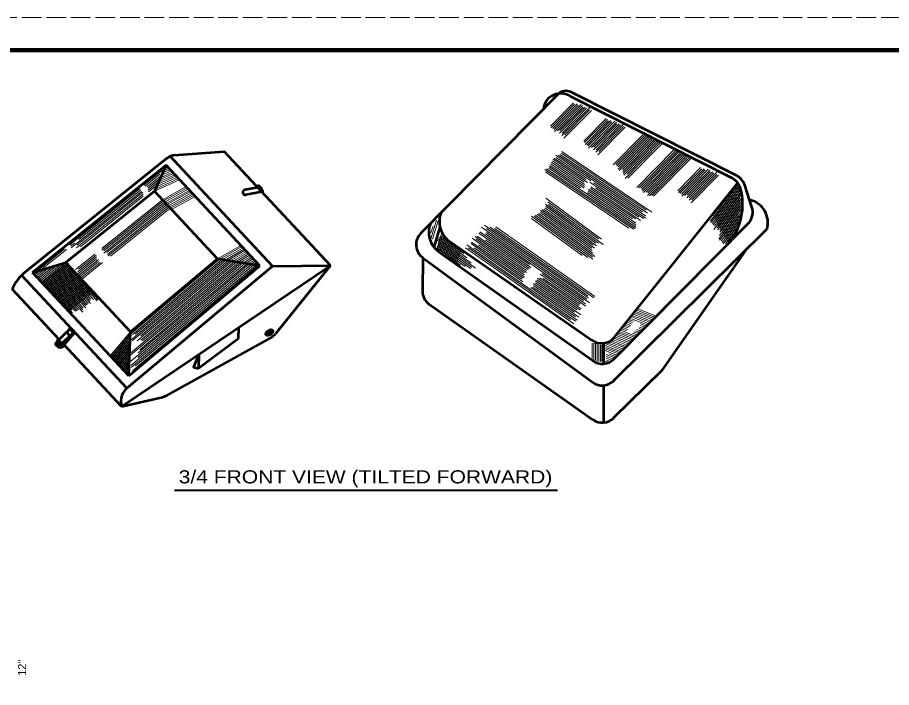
# Model space of a CAD drawing. Extents: x -67 to 613, y -55 to 385.
# Drawn here: x 119.2 to 386.2, y 179.9 to 384.6 of the extents above; entities that cross this region are included whole.
import ezdxf

# ---------------------------------------------------------------- set-up
doc = ezdxf.new("R2010")
doc.units = 0
doc.linetypes.add('LONG_DASHED', pattern=[7.5, 6, -1.5])
doc.layers.add('1', color=7, linetype='Continuous', lineweight=13)
doc.layers.add('61', color=7, linetype='Continuous', lineweight=35)

msp = doc.modelspace()

# ---------------------------------------------------------------- linework, layer by layer
at = {"layer": '1', "lineweight": 53}
for p, q in [((242.429, 318.693), (284.722, 361.553)), ((338.855, 336.269), (288.755, 361.588)), ((337.504, 335.457), (288.089, 360.43)), ((197.065, 308.614), (165.693, 342.257)), ((166.939, 342.485), (182.369, 343.629)), ((214.86, 308.786), (182.369, 343.629)), ((164.707, 341.463), (121.696, 306.859)), ((164.571, 339.428), (123.814, 306.638)), ((164.571, 339.428), (161.056, 331.467)), ((193.249, 308.675), (164.571, 339.428)), ((301.482, 286.796), (339.241, 334.004)), ((161.056, 331.467), (133.971, 309.675)), ((180.282, 310.849), (161.056, 331.467)), ((192.643, 332.611), (188.705, 331.907)), ((193.861, 331.305), (188.969, 330.43)), ((192.643, 332.611), (192.643, 333.478)), ((192.643, 333.478), (193.861, 332.172)), ((192.643, 333.111), (193.861, 331.805)), ((193.861, 331.305), (193.861, 332.172)), ((343.558, 326.638), (341.351, 333.365)), ((248.263, 320.485), (246.399, 314.394)), ((301.399, 280.208), (342.324, 321.525)), ((301.284, 273.599), (348.185, 319.998)), ((250.594, 316.631), (294.693, 285.981)), ((247.916, 312.964), (294.923, 279.733)), ((153.687, 288.533), (180.282, 310.849)), ((193.249, 308.675), (180.282, 310.849)), ((243.028, 311.151), (242.889, 301.051)), ((243.028, 311.151), (294.808, 273.124)), ((123.814, 306.638), (133.971, 309.675)), ((153.687, 288.533), (133.971, 309.675)), ((151.024, 265.729), (214.86, 308.786)), ((153.229, 275.094), (193.249, 308.675)), ((214.86, 308.786), (198.026, 287.947)), ((152.635, 271.333), (120.47, 305.825)), ((153.229, 275.094), (123.814, 306.638)), ((131.907, 286.229), (117.606, 301.565)), ((294.834, 261.694), (245.003, 296.898)), ((134.136, 288.39), (131.684, 286.012)), ((134.136, 288.39), (135.18, 287.313)), ((135.139, 289.525), (136.183, 288.448)), ((153.229, 275.094), (153.687, 288.533)), ((186.673, 289.774), (186.625, 286.395)), ((195.047, 287.697), (197.024, 289.115)), ((195.193, 287.494), (197.17, 288.912)), ((132.433, 284.609), (131.332, 285.71)), ((132.745, 284.951), (131.684, 286.012)), ((135.18, 287.313), (132.745, 284.951)), ((136.466, 288.11), (133.181, 284.291)), ((164.792, 269.106), (196.561, 286.715)), ((186.625, 286.395), (174.495, 277.305)), ((131.996, 283.561), (130.731, 284.719)), ((132.315, 283.962), (130.976, 285.188)), ((133.767, 284.235), (131.996, 283.561)), ((133.181, 284.291), (132.085, 283.874)), ((151.024, 265.729), (133.437, 284.588)), ((298.249, 285.047), (298.249, 278.776)), ((174.556, 281.601), (174.495, 277.305)), ((298.249, 272.177), (298.249, 260.805)), ((151.024, 265.729), (163.493, 268.607))]:
    msp.add_line(p, q, dxfattribs=at)
at = {"layer": '1'}
for p, q in [((282.068, 351.398), (289.033, 358.456)), ((282.248, 350.868), (289.389, 358.105)), ((282.724, 350.639), (290.118, 358.132)), ((283.255, 349.753), (291.355, 357.962)), ((283.175, 350.384), (290.426, 357.732)), ((284.158, 349.957), (291.801, 357.702)), ((284.815, 349.198), (292.654, 357.142)), ((284.908, 350.005), (291.964, 357.155)), ((285.522, 348.492), (293.987, 357.069)), ((285.565, 349.247), (293.058, 356.84)), ((286.127, 347.681), (294.502, 356.168)), ((286.394, 348.663), (293.954, 356.324)), ((292.218, 346.825), (299.033, 353.731)), ((292.423, 346.321), (299.388, 353.38)), ((292.603, 345.792), (299.744, 353.029)), ((293.079, 345.562), (300.474, 353.056)), ((293.531, 345.308), (300.782, 352.656)), ((293.611, 344.677), (301.711, 352.886)), ((294.514, 344.88), (302.157, 352.626)), ((295.17, 344.122), (303.009, 352.066)), ((295.264, 344.928), (302.32, 352.079)), ((295.878, 343.416), (304.342, 351.993)), ((295.92, 344.17), (303.413, 351.764)), ((296.483, 342.605), (304.858, 351.092)), ((296.75, 343.587), (304.309, 351.248)), ((301.143, 339.497), (310.259, 348.735)), ((302.018, 339.672), (310.86, 348.632)), ((302.248, 339.193), (311.41, 348.478)), ((302.677, 338.916), (311.887, 348.25)), ((302.706, 338.233), (312.142, 347.796)), ((302.99, 337.809), (312.645, 347.594)), ((304.007, 338.128), (313.074, 347.316)), ((304.115, 337.525), (313.674, 347.212)), ((304.244, 336.944), (314.103, 346.935)), ((304.375, 336.366), (314.533, 346.66)), ((304.834, 335.407), (315.636, 346.353)), ((305.423, 336.715), (315.158, 346.581)), ((305.608, 335.479), (315.987, 345.998)), ((283.667, 342.454), (311.085, 323.959)), ((283.766, 341.784), (294.327, 334.66)), ((284.512, 342.487), (310.081, 325.239)), ((285.014, 342.751), (311.648, 324.785)), ((285.347, 343.13), (311.215, 325.68)), ((285.519, 343.617), (312.943, 325.118)), ((308.36, 332.574), (319.733, 344.099)), ((309.038, 332.548), (320.384, 344.047)), ((309.565, 332.37), (320.764, 343.72)), ((309.921, 332.019), (321.267, 343.517)), ((310.073, 331.462), (321.496, 343.038)), ((310.401, 331.083), (322.125, 342.963)), ((311.205, 331.185), (322.627, 342.76)), ((311.659, 330.222), (323.485, 342.206)), ((311.73, 331.006), (322.981, 342.407)), ((312.239, 330.097), (323.765, 341.778)), ((164.751, 339.235), (164.417, 339.081)), ((281.958, 339.385), (292.343, 332.379)), ((282.147, 339.86), (292.364, 332.968)), ((282.315, 340.35), (292.398, 333.548)), ((282.581, 340.774), (292.299, 334.219)), ((282.798, 341.231), (293.313, 334.137)), ((283.121, 341.616), (292.848, 335.054)), ((313.013, 330.171), (324.268, 341.576)), ((313.517, 329.969), (324.869, 341.473)), ((163.547, 337.963), (157.813, 333.35)), ((162.718, 336.654), (158.228, 333.042)), ((167.263, 336.541), (162.278, 334.236)), ((166.904, 336.926), (162.584, 334.928)), ((166.546, 337.31), (162.889, 335.62)), ((166.187, 337.695), (163.195, 336.312)), ((165.828, 338.08), (163.501, 337.004)), ((165.469, 338.465), (163.806, 337.696)), ((165.11, 338.85), (164.112, 338.388)), ((280.292, 338.096), (307.327, 319.859)), ((280.463, 337.378), (305.996, 320.154)), ((280.794, 338.361), (307.896, 320.078)), ((281.492, 338.493), (308.131, 320.523)), ((281.625, 339.007), (291.164, 332.572)), ((320.909, 331.638), (327.874, 338.696)), ((321.089, 331.108), (328.23, 338.345)), ((321.565, 330.879), (328.959, 338.372)), ((322.016, 330.624), (329.267, 337.972)), ((322.096, 329.993), (330.196, 338.202)), ((322.999, 330.197), (330.642, 337.942)), ((323.656, 329.438), (331.495, 337.382)), ((323.749, 330.245), (330.805, 337.396)), ((324.364, 328.732), (332.828, 337.31)), ((324.406, 329.487), (331.899, 337.08)), ((324.969, 327.921), (333.344, 336.409)), ((325.235, 328.903), (332.795, 336.564)), ((162.863, 336.129), (158.793, 332.854)), ((162.034, 334.82), (159.101, 332.46)), ((161.984, 334.139), (159.116, 331.831)), ((168.699, 335.001), (161.056, 331.467)), ((168.34, 335.386), (161.362, 332.159)), ((167.981, 335.771), (161.667, 332.851)), ((167.622, 336.156), (161.973, 333.543)), ((294.012, 334.269), (310.456, 323.176)), ((295.285, 334.013), (311.176, 323.294)), ((339.108, 333.857), (340.173, 331.921)), ((156.537, 332.323), (135.164, 315.128)), ((157.037, 331.442), (135.633, 314.222)), ((157.523, 331.191), (137.365, 314.973)), ((156.836, 331.922), (137.935, 316.715)), ((161.35, 332.987), (159.236, 331.286)), ((171.031, 332.5), (163.801, 328.523)), ((171.383, 332.123), (164.153, 328.146)), ((171.734, 331.746), (164.505, 327.769)), ((172.086, 331.369), (164.856, 327.392)), ((293.335, 331.107), (308.098, 321.149)), ((293.552, 331.564), (308.101, 321.75)), ((293.657, 332.096), (307.115, 323.018)), ((294.186, 332.342), (307.951, 323.057)), ((294.305, 332.865), (309.549, 322.582)), ((295.738, 332.502), (309.017, 323.544)), ((330.777, 322.382), (339.77, 333.09)), ((330.831, 323.223), (339.388, 333.412)), ((331.025, 321.899), (339.753, 332.292)), ((331.448, 321.625), (339.86, 331.642)), ((337.039, 331.393), (340.552, 325.008)), ((337.477, 331.634), (340.647, 325.873)), ((337.729, 332.214), (340.703, 326.807)), ((338.074, 332.625), (340.712, 327.829)), ((338.419, 333.036), (340.654, 328.971)), ((338.763, 333.446), (340.499, 330.29)), ((157.55, 330.571), (137.242, 314.232)), ((157.546, 329.926), (138.415, 314.534)), ((163.791, 328.534), (145.056, 313.46)), ((172.438, 330.992), (165.208, 327.014)), ((172.79, 330.615), (165.56, 326.637)), ((173.141, 330.238), (165.912, 326.26)), ((173.493, 329.86), (166.263, 325.883)), ((280.607, 329.315), (297.631, 316.813)), ((331.749, 321.206), (339.921, 330.937)), ((331.901, 319.832), (339.89, 329.345)), ((332.08, 320.823), (340.09, 330.361)), ((332.968, 320.325), (339.971, 328.664)), ((334.626, 328.519), (339.22, 320.167)), ((334.971, 328.93), (339.463, 320.763)), ((335.315, 329.34), (339.691, 321.385)), ((335.66, 329.751), (339.904, 322.036)), ((336.005, 330.161), (340.098, 322.72)), ((336.35, 330.572), (340.273, 323.439)), ((336.695, 330.983), (340.426, 324.2)), ((164.475, 327.8), (145.555, 312.578)), ((164.133, 328.167), (145.612, 313.265)), ((164.817, 327.434), (146.529, 312.72)), ((165.159, 327.067), (146.657, 312.181)), ((165.501, 326.7), (146.861, 311.704)), ((165.843, 326.334), (147.593, 311.651)), ((279.452, 325.821), (295.445, 314.075)), ((280.027, 326.019), (295.015, 315.011)), ((280.347, 326.404), (296.098, 314.836)), ((280.504, 327.53), (296.724, 315.618)), ((280.543, 326.88), (295.842, 315.645)), ((281.254, 328.219), (296.657, 316.908)), ((281.453, 327.453), (298.117, 315.215)), ((332.557, 326.056), (337.514, 317.044)), ((332.902, 326.466), (337.825, 317.517)), ((333.074, 319.674), (339.94, 327.85)), ((333.246, 326.877), (338.125, 318.007)), ((333.591, 327.287), (338.416, 318.516)), ((333.756, 318.931), (340.087, 326.47)), ((333.775, 319.731), (340.069, 327.226)), ((333.936, 327.698), (338.696, 319.045)), ((334.281, 328.109), (338.964, 319.595)), ((276.217, 323.854), (293.383, 311.247)), ((276.265, 323.199), (291.681, 311.877)), ((276.994, 323.904), (294.924, 310.736)), ((277.432, 324.202), (294.855, 311.407)), ((277.933, 324.455), (295.544, 311.521)), ((278.447, 324.698), (294.948, 312.579)), ((278.938, 325.578), (294.6, 314.075)), ((278.948, 324.95), (294.744, 313.349)), ((331.523, 324.824), (336.504, 315.767)), ((331.867, 325.234), (336.866, 316.147)), ((332.212, 325.645), (337.195, 316.587)), ((333.4, 316.952), (339.533, 324.256)), ((333.611, 317.981), (339.99, 325.577)), ((333.687, 316.517), (339.925, 323.944)), ((247.204, 322.618), (245.475, 316.969)), ((246.136, 320.837), (245.513, 318.8)), ((247.682, 322.472), (245.953, 316.823)), ((278.244, 308.42), (260.967, 320.552)), ((293.479, 298.943), (261.884, 321.13)), ((292.627, 300.153), (263.601, 320.535)), ((295.601, 299.286), (265.309, 320.557)), ((334.175, 316.32), (339.406, 322.549)), ((334.415, 315.828), (339.494, 321.877)), ((248.831, 318.876), (247.376, 314.12)), ((249.061, 317.917), (247.703, 313.482)), ((248.293, 317.792), (255.595, 312.429)), ((268.896, 311.318), (259.665, 317.8)), ((275.576, 307.85), (260.137, 318.691)), ((275.969, 308.184), (260.445, 319.085)), ((275.598, 309.056), (262.138, 318.507)), ((293.164, 298.554), (262.441, 320.128)), ((293.449, 299.575), (264.735, 319.739)), ((295.3, 298.887), (265.022, 320.148)), ((334.713, 315.405), (338.808, 320.281)), ((335.475, 315.536), (337.874, 318.392)), ((136.627, 315.663), (135.541, 314.789)), ((247.405, 316.583), (259.09, 308.001)), ((247.576, 315.217), (257.539, 307.9)), ((247.701, 316.986), (257.82, 309.554)), ((247.745, 315.712), (258.007, 308.176)), ((247.997, 317.389), (256.441, 311.187)), ((249.442, 317.453), (248.207, 313.42)), ((249.756, 316.77), (248.592, 312.967)), ((250.15, 316.351), (249.025, 312.676)), ((250.531, 315.887), (249.423, 312.267)), ((250.949, 315.543), (249.799, 311.785)), ((251.392, 315.284), (250.25, 311.553)), ((251.852, 315.077), (250.721, 311.382)), ((275.91, 301.505), (256.494, 315.139)), ((268.997, 307.582), (257.756, 315.475)), ((269.479, 307.854), (257.92, 315.971)), ((268.298, 309.905), (258.044, 317.106)), ((271.994, 308.532), (259.016, 317.645)), ((269.087, 309.962), (259.172, 316.924)), ((274.096, 305.223), (259.998, 315.123)), ((268.494, 312.211), (262.178, 316.646)), ((133.587, 313.859), (125.534, 307.38)), ((134.198, 313.709), (126.893, 307.832)), ((180.282, 310.849), (187.393, 314.954)), ((181.057, 310.719), (187.743, 314.579)), ((181.832, 310.589), (188.093, 314.204)), ((182.607, 310.459), (188.443, 313.828)), ((183.382, 310.329), (188.793, 313.453)), ((184.157, 310.2), (189.143, 313.078)), ((184.932, 310.07), (189.493, 312.703)), ((247.299, 314.179), (254.529, 308.87)), ((247.42, 314.71), (255.959, 308.44)), ((252.33, 314.931), (251.132, 311.017)), ((252.808, 314.785), (251.538, 310.635)), ((253.286, 314.638), (251.974, 310.35)), ((253.764, 314.492), (252.438, 310.158)), ((253.951, 313.392), (252.834, 309.743)), ((254.425, 313.234), (253.247, 309.383)), ((275.672, 301.061), (256.959, 314.202)), ((268.345, 307.428), (258.72, 314.187)), ((143.385, 310.832), (136.878, 305.597)), ((142.801, 312.287), (136.915, 307.552)), ((143.949, 310.645), (137.191, 305.207)), ((143.968, 310.018), (137.505, 304.818)), ((143.358, 311.452), (137.673, 306.878)), ((144.432, 309.749), (137.818, 304.428)), ((143.197, 311.964), (137.884, 307.69)), ((145.205, 309.729), (138.131, 304.039)), ((153.986, 286.173), (182.78, 310.334)), ((154.008, 288.15), (180.835, 310.66)), ((154.265, 285.755), (183.428, 310.225)), ((154.329, 287.767), (181.387, 310.471)), ((155.137, 287.791), (182.131, 310.443)), ((155.8, 285.737), (184.725, 310.008)), ((156.878, 287.294), (184.076, 310.116)), ((156.878, 285.989), (185.373, 309.899)), ((157.394, 285.769), (186.021, 309.79)), ((185.707, 309.94), (189.843, 312.327)), ((186.482, 309.81), (190.192, 311.952)), ((187.257, 309.68), (190.542, 311.577)), ((188.032, 309.55), (190.892, 311.202)), ((188.807, 309.42), (191.243, 310.826)), ((189.582, 309.29), (191.593, 310.451)), ((190.356, 309.16), (191.942, 310.076)), ((273.932, 305.949), (268.298, 309.905)), ((273.56, 308.654), (268.494, 312.211)), ((273.952, 306.546), (269.087, 309.962)), ((126.353, 307.397), (124.498, 305.904)), ((127.623, 307.777), (124.84, 305.538)), ((128.893, 308.157), (125.182, 305.171)), ((130.162, 308.536), (125.524, 304.804)), ((131.432, 308.916), (125.865, 304.438)), ((132.701, 309.296), (126.207, 304.071)), ((133.971, 309.675), (126.549, 303.704)), ((134.284, 309.286), (126.891, 303.338)), ((134.598, 308.896), (127.233, 302.971)), ((134.997, 308.575), (127.575, 302.605)), ((135.338, 308.209), (127.917, 302.238)), ((135.68, 307.842), (128.259, 301.871)), ((136.022, 307.476), (128.601, 301.505)), ((136.364, 307.109), (128.943, 301.138)), ((140.526, 296.78), (130.846, 307.161)), ((140.788, 297.233), (131.237, 307.476)), ((141.514, 297.188), (131.627, 307.79)), ((141.42, 298.022), (132.018, 308.104)), ((141.651, 298.507), (132.408, 308.418)), ((142.383, 298.454), (132.799, 308.733)), ((143.527, 297.961), (133.19, 309.047)), ((143.893, 298.302), (133.58, 309.361)), ((153.743, 281.4), (187.318, 309.573)), ((153.75, 282.059), (186.67, 309.682)), ((153.816, 278.198), (190.464, 308.949)), ((153.838, 279.522), (189.263, 309.247)), ((153.904, 277.619), (191.208, 308.921)), ((154.42, 276.746), (192.45, 308.658)), ((155.29, 278.13), (191.856, 308.812)), ((155.964, 280.653), (189.815, 309.058)), ((156.113, 282.084), (188.519, 309.275)), ((156.526, 283.082), (187.966, 309.464)), ((187.037, 303.463), (192.867, 308.355)), ((191.131, 309.03), (192.292, 309.7)), ((191.906, 308.9), (192.642, 309.325)), ((192.681, 308.77), (192.992, 308.95)), ((273.574, 303.756), (268.345, 307.428)), ((273.273, 304.579), (268.997, 307.581)), ((273.715, 304.88), (269.479, 307.854)), ((274.647, 306.669), (271.994, 308.532)), ((275.164, 307.528), (273.56, 308.654)), ((293.971, 297.376), (278.244, 308.42)), ((125.084, 307.017), (124.156, 306.271)), ((136.905, 294.799), (127.721, 304.647)), ((137.443, 294.954), (128.112, 304.962)), ((137.873, 295.227), (128.502, 305.276)), ((139.163, 294.576), (128.893, 305.59)), ((139.211, 295.258), (129.283, 305.904)), ((136.706, 306.742), (129.285, 300.771)), ((137.048, 306.376), (129.626, 300.405)), ((139.287, 295.909), (129.674, 306.219)), ((137.39, 306.009), (129.968, 300.038)), ((140.031, 295.845), (130.065, 306.533)), ((137.732, 305.642), (130.31, 299.671)), ((140.059, 296.548), (130.455, 306.847)), ((138.074, 305.276), (130.652, 299.305)), ((138.416, 304.909), (130.994, 298.938)), ((138.758, 304.542), (131.336, 298.571)), ((280.267, 302.723), (277.879, 304.399)), ((290.789, 296.556), (278.768, 304.997)), ((292.802, 296.364), (278.882, 306.138)), ((292.668, 297.069), (279.425, 306.369)), ((291.038, 296.992), (279.828, 304.864)), ((135.985, 294.319), (126.94, 304.019)), ((135.855, 295.192), (127.33, 304.333)), ((139.1, 304.176), (131.678, 298.205)), ((139.441, 303.809), (132.02, 297.838)), ((139.783, 303.442), (132.362, 297.471)), ((140.125, 303.076), (132.704, 297.105)), ((140.467, 302.709), (133.046, 296.738)), ((140.809, 302.342), (133.387, 296.371)), ((141.151, 301.976), (133.729, 296.005)), ((290.202, 292.08), (276.034, 302.029)), ((289.605, 293.11), (276.648, 302.209)), ((290.623, 293.006), (276.825, 302.696)), ((289.372, 294.496), (276.865, 303.278)), ((291.316, 293.741), (277.407, 303.508)), ((279.29, 302.798), (277.444, 304.094)), ((278.702, 302.082), (279.042, 301.833)), ((290.048, 295.243), (279.29, 302.798)), ((291.041, 295.157), (280.267, 302.722)), ((141.493, 301.609), (134.071, 295.638)), ((141.835, 301.242), (134.413, 295.272)), ((142.177, 300.876), (134.755, 294.905)), ((289.12, 291.007), (275.385, 300.652)), ((288.077, 292.35), (275.615, 301.101)), ((289.69, 291.829), (275.91, 301.505)), ((307.389, 293.909), (312.301, 292.016)), ((307.786, 294.292), (313.015, 292.277)), ((307.973, 294.756), (313.588, 292.592)), ((308.634, 295.037), (313.606, 293.121)), ((308.926, 295.46), (313.868, 293.556)), ((305.407, 291.458), (306.77, 290.933)), ((306.046, 291.747), (307.066, 291.354)), ((306.166, 292.237), (307.38, 291.769)), ((306.743, 292.551), (311.519, 290.71)), ((307.023, 292.979), (311.698, 291.177)), ((307.15, 293.466), (311.89, 291.639)), ((153.687, 288.533), (147.553, 281.181)), ((303.413, 288.476), (307.577, 286.871)), ((303.672, 288.911), (307.989, 287.248)), ((303.981, 289.328), (305.329, 288.809)), ((304.271, 289.752), (305.626, 289.23)), ((304.649, 290.143), (305.727, 289.727)), ((305.066, 290.518), (306.223, 290.072)), ((305.257, 290.98), (306.594, 290.465)), ((307.524, 288.499), (308.86, 287.984)), ((307.966, 288.864), (309.301, 288.35)), ((308.362, 289.247), (309.641, 288.754)), ((309.077, 289.508), (309.713, 289.263)), ((309.253, 289.976), (310.09, 289.653)), ((309.468, 290.429), (310.538, 290.017)), ((309.534, 290.939), (311.066, 290.349)), ((153.659, 287.719), (147.937, 280.861)), ((153.631, 286.905), (148.24, 280.444)), ((153.603, 286.092), (148.584, 280.075)), ((153.518, 283.582), (151.427, 285.824)), ((153.542, 284.289), (151.75, 286.211)), ((153.566, 284.996), (152.072, 286.598)), ((153.59, 285.703), (152.395, 286.985)), ((153.614, 286.411), (152.718, 287.372)), ((153.638, 287.118), (153.041, 287.759)), ((153.663, 287.825), (153.364, 288.146)), ((300.826, 285.721), (304.769, 284.202)), ((301.282, 286.082), (305.364, 284.508)), ((301.711, 286.452), (305.573, 284.964)), ((301.987, 286.882), (306.187, 285.263)), ((302.342, 287.281), (306.254, 285.773)), ((302.665, 287.692), (306.95, 286.041)), ((302.977, 288.107), (307.338, 286.427)), ((307.072, 288.137), (308.46, 287.602)), ((153.576, 285.278), (148.928, 279.707)), ((153.349, 278.631), (149.167, 283.115)), ((153.548, 284.464), (149.271, 279.338)), ((153.373, 279.338), (149.49, 283.502)), ((153.52, 283.65), (149.615, 278.969)), ((153.397, 280.045), (149.813, 283.889)), ((153.422, 280.752), (150.136, 284.276)), ((153.446, 281.46), (150.458, 284.663)), ((153.47, 282.167), (150.781, 285.05)), ((153.494, 282.874), (151.104, 285.437)), ((294.749, 285.047), (294.749, 280.466)), ((295.249, 285.047), (295.249, 280.008)), ((295.749, 285.047), (295.749, 279.794)), ((296.249, 285.047), (296.249, 279.549)), ((296.749, 284.532), (296.749, 279.519)), ((297.249, 284.502), (297.249, 279.427)), ((297.749, 284.41), (297.749, 279.427)), ((298.684, 283.332), (302.443, 281.883)), ((298.719, 284.39), (303.438, 282.572)), ((298.918, 284.849), (303.505, 283.082)), ((298.928, 283.774), (302.962, 282.219)), ((299.634, 285.109), (304.144, 283.371)), ((300.29, 285.392), (304.638, 283.717)), ((153.253, 275.802), (147.876, 281.568)), ((153.277, 276.509), (148.241, 281.909)), ((153.301, 277.216), (148.521, 282.342)), ((153.325, 277.923), (148.844, 282.728)), ((153.493, 282.837), (149.959, 278.601)), ((153.465, 282.023), (150.302, 278.232)), ((153.437, 281.209), (150.646, 277.864)), ((153.409, 280.395), (150.99, 277.495)), ((298.693, 282.793), (302.192, 281.444)), ((298.919, 281.098), (300.91, 280.331)), ((299.034, 281.589), (301.328, 280.705)), ((299.061, 280.507), (300.327, 280.02)), ((299.838, 281.815), (301.662, 281.113)), ((153.382, 279.582), (151.333, 277.127)), ((153.354, 278.768), (151.677, 276.758)), ((153.326, 277.954), (152.021, 276.39)), ((298.76, 279.551), (299.591, 279.231)), ((299.219, 279.91), (299.821, 279.679)), ((153.298, 277.14), (152.364, 276.021)), ((153.271, 276.327), (152.708, 275.653))]:
    msp.add_line(p, q, dxfattribs=at)
at = {"layer": '1', "lineweight": 40}
msp.add_line((167.143, 240.135), (284.122, 240.135), dxfattribs=at)
at = {"layer": '1'}
for points in [[(170.679, 332.878), (163.45, 328.9), (144.971, 314.034)], [(292.089, 298.087), (277.787, 308.13), (262.496, 318.867)], [(275.385, 300.652), (268.529, 305.467), (256.069, 314.216)], [(274.679, 307.257), (272.482, 308.8), (268.896, 311.318)], [(291.404, 295.513), (282.139, 302.019), (278.039, 304.898)]]:
    msp.add_lwpolyline(points, dxfattribs=at)
at = {"layer": '1', "lineweight": 53}
for points in [[(341.542, 313.426), (315.906, 276.668), (301.227, 262.215)], [(152.635, 271.333), (197.065, 308.614), (214.86, 308.786)], [(174.556, 281.601), (172.934, 277.689), (174.495, 277.305)]]:
    msp.add_lwpolyline(points, dxfattribs=at)
for centre, radius, start, end in [((285.1, 356.088), 5.271, 55.45095, 174.18638), ((286.768, 358.108), 4.007, 60.28803, 120.71357), ((167.841, 337.567), 5, 100.4008, 128.81759), ((335.248, 330.995), 5, 15.07312, 63.18927), ((336.6, 331.806), 5, 18.17013, 63.18958), ((188.765, 331.156), 0.754, 94.57729, 285.70271), ((193.603, 331.327), 0.543, 329.79385, 61.6922), ((322.147, 327.466), 18.568, 320.7657, 15.07312), ((341.265, 321.86), 7.167, 344.94334, 75.45461), ((338.808, 325.079), 5, 314.69118, 18.17057), ((255.445, 322.198), 7.384, 157.88916, 228.93353), ((252.078, 318.901), 7.25, 157.67897, 234.96895), ((245.988, 315.181), 5, 135.38136, 233.70593), ((128.914, 297.056), 12.174, 126.36545, 158.25906), ((247.888, 300.982), 5, 179.20851, 234.75943), ((132.774, 290.603), 2.599, 301.61144, 335.47975), ((135.221, 288.56), 0.969, 353.37461, 94.84721), ((133.975, 289.388), 2.399, 300.15332, 336.93786), ((135.219, 288.196), 1.25, 356.04932, 56.10446), ((131.645, 285.702), 0.313, 82.91008, 178.42882), ((194.137, 291.089), 5, 299.00019, 321.06979), ((297.653, 290.011), 5, 233.70535, 319.97622), ((131.964, 284.375), 1.28, 111.86801, 164.43877), ((132.231, 283.663), 0.257, 124.68143, 203.51235), ((132.435, 284.921), 0.311, 269.67074, 5.67221), ((133.115, 284.788), 0.502, 193.01078, 277.55203), ((297.882, 283.763), 5, 233.70593, 314.69088), ((297.882, 277.164), 5, 233.70564, 314.69135), ((156.068, 267.319), 5.289, 124.21058, 197.49633), ((162.368, 273.479), 5, 283.00061, 299.00053), ((297.842, 265.789), 5, 234.75966, 314.55799)]:
    msp.add_arc(centre, radius, start, end, dxfattribs=at)
at = {"layer": '1'}
msp.add_arc((167.841, 337.567), 5, 100.40084, 128.81858, dxfattribs=at)
at = {"layer": '1', "lineweight": 53}
msp.add_ellipse((196.108, 288.305), major_axis=(1.006, 0.722), ratio=0.545523, dxfattribs=at)
at = {"layer": '61', "linetype": 'LONG_DASHED', "lineweight": 13}
msp.add_line((-66.959, 384.56), (613.061, 384.56), dxfattribs=at)
at = {"layer": '61', "lineweight": 158}
msp.add_lwpolyline([(602.081, 374.56), (-36.959, 374.56), (-36.959, -45.46)], dxfattribs=at)

# ---------------------------------------------------------------- texts
at = {"layer": '1', "width": 1.2}
msp.add_text('3/4 FRONT VIEW (TILTED FORWARD)', height=4, dxfattribs=at).set_placement((168.458, 242.239))
at = {"layer": '1'}
msp.add_text('12"', height=2.5, rotation=90, dxfattribs=at).set_placement((121.852, 183.464))

doc.saveas('drawing.dxf')
